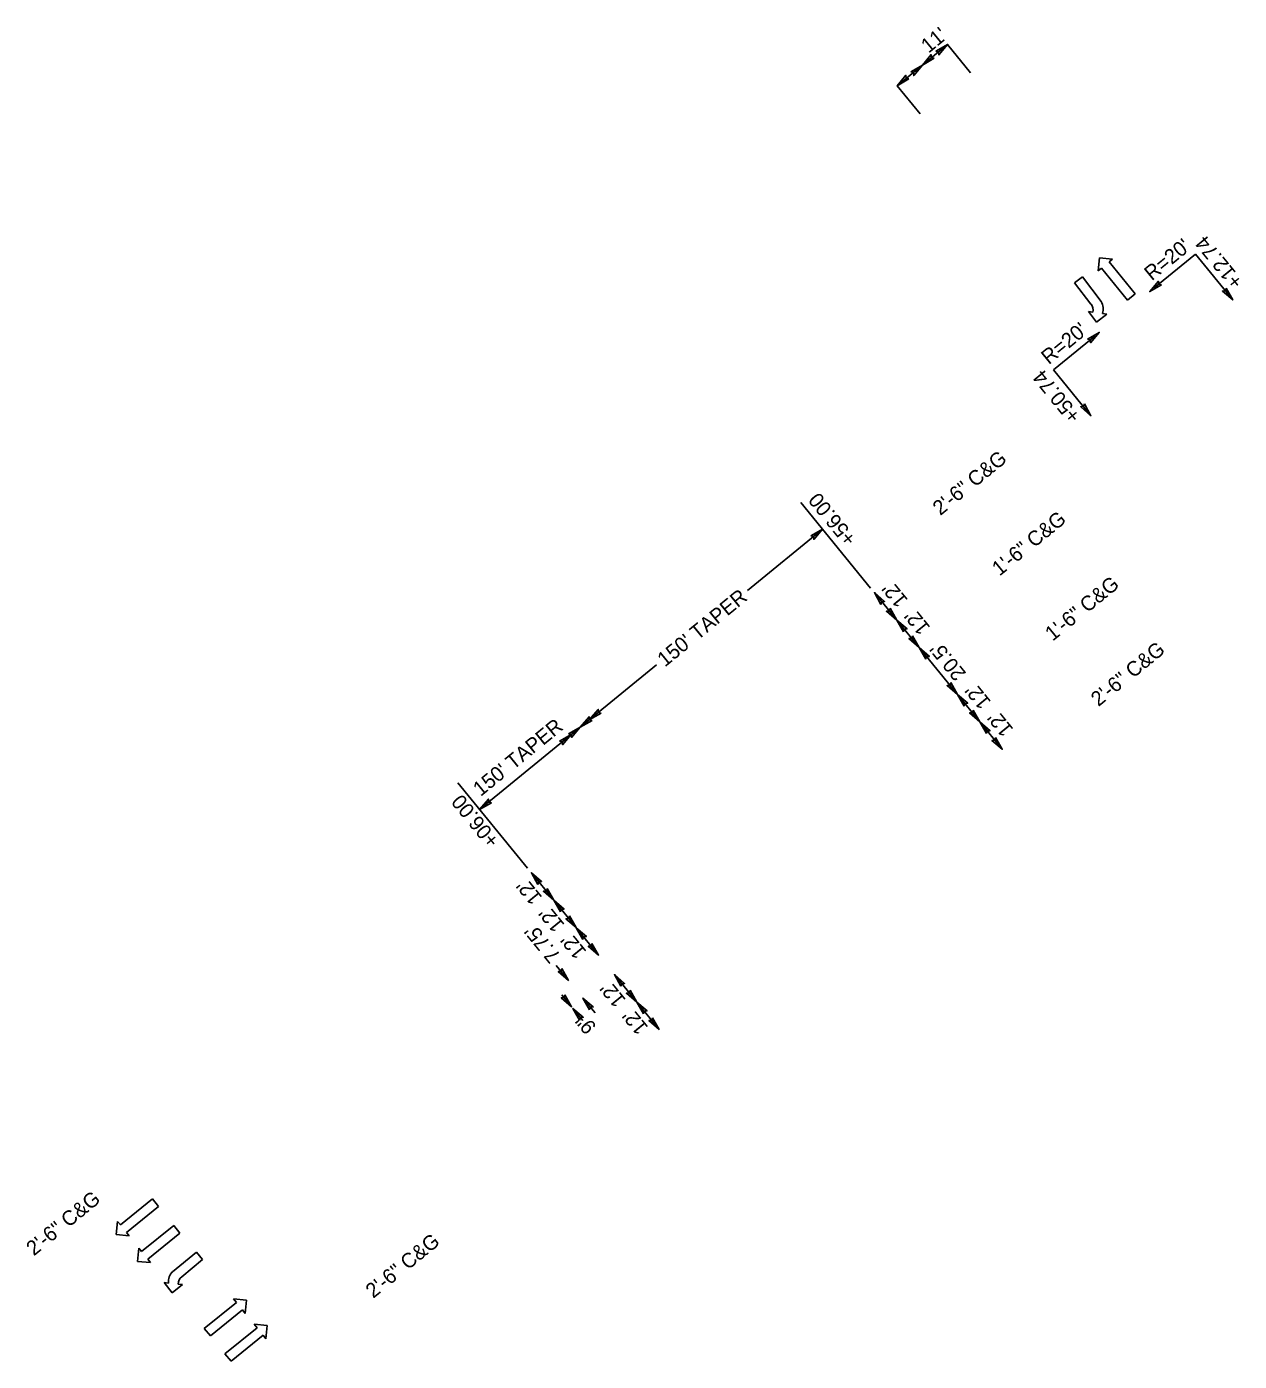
# Model space of a CAD drawing. Extents: x 2320991 to 2332664, y 598057 to 612602.
# Drawn here: x 2324350.9 to 2324761.7, y 600212.8 to 600664.7 of the extents above; entities that cross this region are included whole.
import ezdxf

# ---------------------------------------------------------------- set-up
doc = ezdxf.new("R2010")
doc.units = 0
for name, color, linetype in [('Prop Dimension', 7, 'Continuous'), ('Prop Dimension Text', 7, 'Continuous'), ('Prop Lane Arrow CELL', 7, 'Continuous'), ('Prop Terminator CELL', 7, 'Continuous')]:
    doc.layers.add(name, color=color, linetype=linetype)

msp = doc.modelspace()

# ---------------------------------------------------------------- linework, layer by layer
at = {"layer": 'Prop Dimension'}
for p, q in [((2324645.83, 600644.75), (2324662.85, 600658.7)), ((2324732.9, 600576.29), (2324746.84, 600587.68)), ((2324759.47, 600572.21), (2324746.84, 600587.68)), ((2324712.72, 600559.9), (2324698.78, 600548.51)), ((2324711.45, 600533), (2324698.78, 600548.51)), ((2324613.16, 600503.58), (2324636.8, 600474.64)), ((2324595.08, 600473.78), (2324620.53, 600494.55)), ((2324638.06, 600473.09), (2324645.65, 600463.79)), ((2324645.65, 600463.79), (2324653.24, 600454.5)), ((2324653.24, 600454.5), (2324666.2, 600438.62)), ((2324504.34, 600399.69), (2324564.25, 600448.6)), ((2324666.2, 600438.62), (2324673.79, 600429.32)), ((2324673.79, 600429.32), (2324681.38, 600420.02)), ((2324496.96, 600408.72), (2324520.6, 600379.77)), ((2324529.45, 600368.93), (2324521.86, 600378.22)), ((2324537.04, 600359.63), (2324529.45, 600368.93)), ((2324544.64, 600350.32), (2324537.05, 600359.62)), ((2324530.32, 600346.82), (2324534.44, 600341.78)), ((2324557.57, 600334.44), (2324549.98, 600343.73)), ((2324532.18, 600336.93), (2324535.49, 600332.87)), ((2324539.34, 600335.78), (2324543.45, 600330.74)), ((2324565.16, 600325.14), (2324557.57, 600334.44)), ((2324535.97, 600332.29), (2324539.28, 600328.24))]:
    msp.add_line(p, q, dxfattribs=at)
at = {"layer": 'Prop Dimension Text'}
for p, q in [((2324670.65, 600649.14), (2324662.84, 600658.69)), ((2324653.63, 600635.2), (2324645.83, 600644.75))]:
    msp.add_line(p, q, dxfattribs=at)
at = {"layer": 'Prop Lane Arrow CELL'}
for p, q in [((2324713.86, 600582.06), (2324714.28, 600586.46)), ((2324715.03, 600583), (2324713.86, 600582.06)), ((2324714.28, 600586.46), (2324718.75, 600586.03)), ((2324723.85, 600572.13), (2324715.03, 600583)), ((2324718.75, 600586.03), (2324717.59, 600585.08)), ((2324717.59, 600585.08), (2324726.41, 600574.21)), ((2324705.9, 600578.02), (2324708.52, 600580.03)), ((2324708.52, 600580.03), (2324714.93, 600571.65)), ((2324711.45, 600570.75), (2324705.9, 600578.02)), ((2324726.41, 600574.21), (2324723.85, 600572.13)), ((2324713.36, 600564.72), (2324710.59, 600568.27)), ((2324710.59, 600568.27), (2324712.06, 600568.07)), ((2324716.83, 600567.43), (2324713.36, 600564.72)), ((2324715.35, 600567.63), (2324716.83, 600567.43)), ((2324382.63, 600258.98), (2324393.5, 600267.8)), ((2324393.5, 600267.8), (2324395.58, 600265.24)), ((2324395.58, 600265.24), (2324384.7, 600256.41)), ((2324381.25, 600255.67), (2324381.68, 600260.14)), ((2324381.68, 600260.14), (2324382.63, 600258.98)), ((2324389.83, 600249.93), (2324400.7, 600258.75)), ((2324400.7, 600258.75), (2324402.78, 600256.19)), ((2324385.65, 600255.25), (2324381.25, 600255.67)), ((2324384.7, 600256.41), (2324385.65, 600255.25)), ((2324402.78, 600256.19), (2324391.91, 600247.37)), ((2324388.46, 600246.62), (2324388.89, 600251.09)), ((2324388.89, 600251.09), (2324389.83, 600249.93)), ((2324408.42, 600249.76), (2324400.24, 600243.09)), ((2324410.5, 600247.21), (2324408.42, 600249.76)), ((2324392.86, 600246.2), (2324388.46, 600246.62)), ((2324391.91, 600247.37), (2324392.86, 600246.2)), ((2324403.42, 600241.42), (2324410.5, 600247.21)), ((2324398.9, 600239.28), (2324397.42, 600239.43)), ((2324397.42, 600239.43), (2324400.17, 600235.99)), ((2324400.17, 600235.99), (2324403.68, 600238.8)), ((2324403.68, 600238.8), (2324402.21, 600238.95)), ((2324411.06, 600223.91), (2324421.93, 600232.73)), ((2324421.93, 600232.73), (2324420.99, 600233.9)), ((2324420.99, 600233.9), (2324425.39, 600233.47)), ((2324425.39, 600233.47), (2324424.96, 600229)), ((2324424.01, 600230.17), (2324413.14, 600221.35)), ((2324424.96, 600229), (2324424.01, 600230.17)), ((2324413.14, 600221.35), (2324411.06, 600223.91)), ((2324418.06, 600215.34), (2324428.93, 600224.16)), ((2324431.01, 600221.6), (2324420.14, 600212.78)), ((2324428.93, 600224.16), (2324427.98, 600225.33)), ((2324427.98, 600225.33), (2324432.38, 600224.9)), ((2324431.95, 600220.43), (2324431.01, 600221.6)), ((2324432.38, 600224.9), (2324431.95, 600220.43)), ((2324420.14, 600212.78), (2324418.06, 600215.34))]:
    msp.add_line(p, q, dxfattribs=at)
for centre, radius, start, end in [((2324708.87, 600568.77), 3.27, 347.7553, 37.4135), ((2324710.33, 600569.13), 5.25, 343.4257, 28.7374), ((2324404.13, 600239.58), 5.25, 137.9041, 183.2158), ((2324405.47, 600238.89), 3.27, 129.228, 178.8862)]:
    msp.add_arc(centre, radius, start, end, dxfattribs=at)
at = {"layer": 'Prop Terminator CELL'}
for points in [[(2324658.27, 600654.05), (2324654.34, 600651.73), (2324657.27, 600655.27), (2324657.35, 600654.28)], [(2324658.92, 600656.38), (2324662.85, 600658.7), (2324659.92, 600655.16), (2324659.84, 600656.14)], [(2324650.41, 600649.41), (2324654.34, 600651.73), (2324651.41, 600648.19), (2324651.33, 600649.17)], [(2324649.76, 600647.07), (2324645.83, 600644.75), (2324648.76, 600648.29), (2324648.84, 600647.31)], [(2324735.33, 600577.27), (2324731.35, 600575.03), (2324734.35, 600578.51), (2324734.41, 600577.53)], [(2324757.23, 600576.18), (2324759.47, 600572.21), (2324755.99, 600575.21), (2324756.98, 600575.27)], [(2324710.29, 600558.92), (2324714.27, 600561.17), (2324711.27, 600557.68), (2324711.21, 600558.67)], [(2324709.2, 600536.97), (2324711.45, 600533), (2324707.97, 600536), (2324708.95, 600536.06)], [(2324616.56, 600492.31), (2324620.53, 600494.55), (2324617.54, 600491.07), (2324617.47, 600492.06)], [(2324640.31, 600469.11), (2324638.06, 600473.09), (2324641.54, 600470.09), (2324640.56, 600470.03)], [(2324643.4, 600467.77), (2324645.65, 600463.79), (2324642.17, 600466.79), (2324643.15, 600466.85)], [(2324647.89, 600459.82), (2324645.65, 600463.79), (2324649.13, 600460.79), (2324648.15, 600460.73)], [(2324650.99, 600458.47), (2324653.24, 600454.5), (2324649.76, 600457.49), (2324650.74, 600457.56)], [(2324655.48, 600450.52), (2324653.24, 600454.5), (2324656.72, 600451.5), (2324655.74, 600451.44)], [(2324663.96, 600442.59), (2324666.2, 600438.62), (2324662.72, 600441.61), (2324663.7, 600441.68)], [(2324668.45, 600434.64), (2324666.2, 600438.62), (2324669.68, 600435.62), (2324668.7, 600435.56)], [(2324542.42, 600429.78), (2324538.44, 600427.53), (2324541.44, 600431.02), (2324541.5, 600430.03)], [(2324545.48, 600432.28), (2324541.5, 600430.03), (2324544.5, 600433.51), (2324544.56, 600432.53)], [(2324671.55, 600433.3), (2324673.79, 600429.32), (2324670.31, 600432.32), (2324671.29, 600432.38)], [(2324676.04, 600425.34), (2324673.79, 600429.32), (2324677.27, 600426.32), (2324676.29, 600426.26)], [(2324531.41, 600422.79), (2324535.38, 600425.04), (2324532.38, 600421.56), (2324532.32, 600422.54)], [(2324534.47, 600425.29), (2324538.44, 600427.53), (2324535.44, 600424.05), (2324535.38, 600425.04)], [(2324679.13, 600424), (2324681.38, 600420.02), (2324677.9, 600423.02), (2324678.88, 600423.08)], [(2324508.31, 600401.94), (2324504.34, 600399.69), (2324507.34, 600403.17), (2324507.4, 600402.19)], [(2324524.11, 600374.25), (2324521.86, 600378.22), (2324525.34, 600375.22), (2324524.36, 600375.16)], [(2324527.2, 600372.9), (2324529.45, 600368.93), (2324525.97, 600371.93), (2324526.95, 600371.99)], [(2324531.7, 600364.95), (2324529.45, 600368.93), (2324532.93, 600365.93), (2324531.95, 600365.87)], [(2324534.79, 600363.61), (2324537.04, 600359.63), (2324533.56, 600362.63), (2324534.54, 600362.69)], [(2324539.3, 600355.64), (2324537.05, 600359.62), (2324540.53, 600356.62), (2324539.55, 600356.56)], [(2324542.39, 600354.3), (2324544.64, 600350.32), (2324541.16, 600353.32), (2324542.14, 600353.38)], [(2324532.19, 600345.76), (2324534.44, 600341.78), (2324530.95, 600344.78), (2324531.94, 600344.84)], [(2324552.23, 600339.76), (2324549.98, 600343.73), (2324553.46, 600340.73), (2324552.48, 600340.67)], [(2324533.25, 600336.85), (2324535.49, 600332.87), (2324532.01, 600335.87), (2324533, 600335.93)], [(2324541.58, 600331.8), (2324539.34, 600335.78), (2324542.82, 600332.78), (2324541.83, 600332.72)], [(2324555.33, 600338.41), (2324557.57, 600334.44), (2324554.09, 600337.44), (2324555.07, 600337.5)], [(2324559.82, 600330.46), (2324557.57, 600334.44), (2324561.05, 600331.44), (2324560.07, 600331.38)], [(2324538.21, 600328.32), (2324535.97, 600332.29), (2324539.45, 600329.29), (2324538.47, 600329.23)], [(2324562.91, 600329.12), (2324565.16, 600325.14), (2324561.68, 600328.14), (2324562.66, 600328.2)]]:
    msp.add_lwpolyline(points, close=True, dxfattribs=at)

# ---------------------------------------------------------------- texts
at = {"layer": 'Prop Dimension'}
for s, p in [('+12.74', (2324763.28, 600578.41)), ('+50.74', (2324708.25, 600533)), ('+56.00', (2324632.28, 600491.42)), ('+06.00', (2324511.33, 600389.21))]:
    msp.add_text(s, height=5, rotation=129.228, dxfattribs=at).set_placement(p)
at = {"layer": 'Prop Dimension Text'}
for s, rotation, p in [("11'", 39.3225, (2324656.43, 600655.55)), ("R=20'", 39.228, (2324732.06, 600578.47)), ("R=20'", 39.228, (2324697.15, 600550.09)), ('2\'-6" C&G', 39.228, (2324660.4, 600498.98)), ('1\'-6" C&G', 39.228, (2324680.47, 600478.49)), ("12'", 129.228, (2324649.66, 600470.6)), ('1\'-6" C&G', 39.228, (2324698.46, 600456.46)), ("150' TAPER", 39.228, (2324567.11, 600447.71)), ("12'", 129.228, (2324657.25, 600461.3)), ("20.5'", 129.228, (2324669.38, 600445.78)), ('2\'-6" C&G', 39.228, (2324713.98, 600434.3)), ("12'", 129.228, (2324677.81, 600436.13)), ("150' TAPER", 39.228, (2324504.68, 600403.86)), ("12'", 129.228, (2324685.4, 600426.83)), ("12'", 129.228, (2324525.77, 600369.92)), ("12'", 129.228, (2324533.36, 600360.63)), ("7.75'", 129.228, (2324532.05, 600350.2)), ("12'", 129.228, (2324540.78, 600351.55)), ("12'", 129.228, (2324554.1, 600335.19)), ("12'", 129.228, (2324561.69, 600325.89)), ('9"', 129.228, (2324544.16, 600326.15)), ('2\'-6" C&G', 39.228, (2324353.32, 600248.28)), ('2\'-6" C&G', 39.228, (2324468.29, 600233.91))]:
    msp.add_text(s, height=5, rotation=rotation, dxfattribs=at).set_placement(p)

doc.saveas('drawing.dxf')
